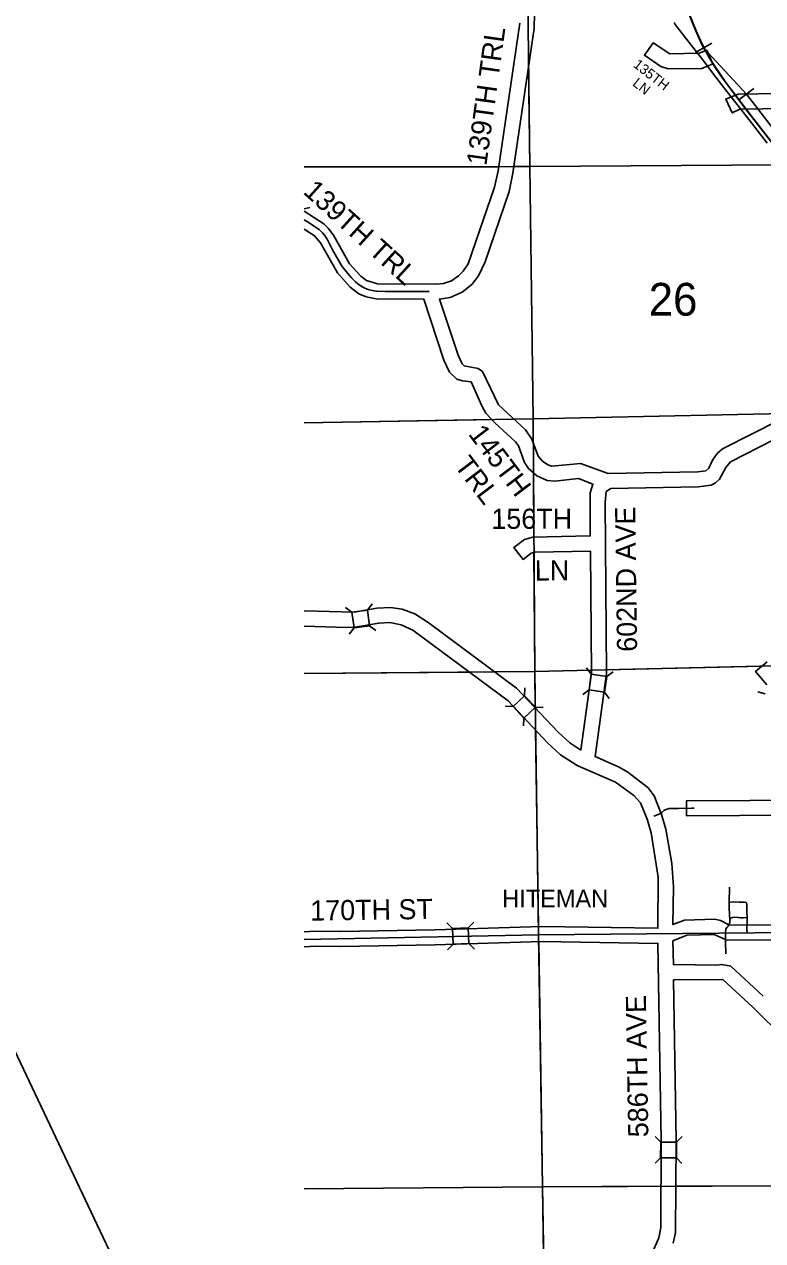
# Model space of a CAD drawing. Extents: x 10133 to 81668, y 5524 to 11018.
# Drawn here: x 14867 to 15234, y 8660 to 9263 of the extents above; entities that cross this region are included whole.
import ezdxf

# ---------------------------------------------------------------- set-up
doc = ezdxf.new("R2010")
doc.units = 0
doc.layers.add('Default', color=7, linetype='Continuous')
doc.layers.add('DisCLMLSUR', color=7, linetype='Continuous')

msp = doc.modelspace()

# ---------------------------------------------------------------- linework, layer by layer
at = {"layer": 'Default'}
for p, q in [((15200.49, 9249.38), (15208.67, 9253.96)), ((15222.05, 9225.78), (15229.55, 9231.4)), ((15006.1, 9171.72), (15008.99, 9172.37)), ((15029.84, 8971.49), (15026.72, 8973.85)), ((15037.59, 8972.57), (15039.95, 8975.69)), ((15030.92, 8963.74), (15028.56, 8960.62)), ((15038.67, 8964.82), (15041.79, 8962.46)), ((15148.73, 8940.71), (15146.38, 8943.84)), ((15156.48, 8939.6), (15159.61, 8941.95)), ((15115.64, 8930.05), (15115.78, 8933.96)), ((15147.63, 8932.96), (15144.5, 8930.61)), ((15155.37, 8931.86), (15157.72, 8928.73)), ((15235.18, 8930.94), (15231.43, 8932.07)), ((15109.91, 8924.72), (15106, 8924.86)), ((15120.97, 8924.32), (15124.88, 8924.18)), ((15115.24, 8918.99), (15115.1, 8915.08)), ((15079.84, 8814.61), (15077, 8817.3)), ((15087.67, 8814.84), (15090.35, 8817.69)), ((15080.08, 8806.79), (15077.39, 8803.94)), ((15087.9, 8807.02), (15090.74, 8804.34)), ((15183.28, 8708.55), (15180.54, 8711.35)), ((15191.11, 8708.48), (15193.9, 8711.23)), ((15183.21, 8700.73), (15180.42, 8697.99)), ((15191.04, 8700.66), (15193.78, 8697.87))]:
    msp.add_line(p, q, dxfattribs=at)
for points in [[(15308.74, 9284.89), (15310.88, 9134.18), (15309.62, 9131.25), (15307.07, 9129.14), (15304.36, 9128.64), (15294.54, 9128.72), (15290.44, 9126.84), (15287.3, 9133.64), (15293.09, 9136.14), (15303.47, 9136.14), (15302.03, 9222.4), (15222.5, 9221.13), (15218.75, 9219.37), (15215.57, 9226.16), (15221.63, 9228.62), (15301.85, 9229.9), (15299.87, 9396.97)], [(15116.72, 9317.83), (15118.18, 9192.67)], [(15376.46, 9026.55), (15227.85, 9218.32), (15215.51, 9234.43), (15207.49, 9246.48), (15203.98, 9253.08), (15201.14, 9259.29), (15192.64, 9280.57)], [(15120.76, 9276.61), (15120.45, 9261.26), (15109.87, 9189.44), (15107.94, 9180.34), (15096.11, 9145.44), (15092.8, 9138.48), (15089.43, 9134.22), (15084.7, 9130.38), (15078.62, 9127.72), (15073.37, 9126.93), (15082.58, 9099.07), (15084.63, 9094.81), (15085.55, 9093.84), (15092.65, 9092.53), (15094.67, 9091), (15102.68, 9074.49), (15116.02, 9062.03), (15119.26, 9057.46), (15122.33, 9049), (15124.55, 9046.42), (15127.11, 9044.71), (15129.24, 9044.08), (15143.48, 9045.28), (15157.21, 9040.31), (15201.69, 9041.2), (15205.72, 9041.69), (15207.11, 9042.96), (15208.99, 9046.93), (15211.29, 9050.34), (15213.92, 9052.55), (15242.75, 9067.24)], [(15197.04, 9269.01), (15199.73, 9262.37), (15201.67, 9257.74), (15204, 9252.71), (15207.79, 9245.94), (15210.65, 9241.42), (15213.88, 9236.66), (15221.86, 9226.01), (15225.4, 9221.29), (15238.22, 9204.83)], [(15006.1, 9170.58), (15015.99, 9164.24), (15018.14, 9162.2), (15020.65, 9158.71), (15028.64, 9144.47), (15034.24, 9138.24), (15037.07, 9136.09), (15042.57, 9134.55), (15071.56, 9134.32), (15075.28, 9134.66), (15079.34, 9135.96), (15082.89, 9138.41), (15085.18, 9140.81), (15087.65, 9144.48), (15100.77, 9182.53), (15102.46, 9190.56), (15113.23, 9263.88)], [(15236.12, 9204.25), (15231.16, 9210.78), (15226.04, 9217.35), (15220.56, 9224.35), (15216.3, 9229.8), (15210.69, 9237.05), (15206.46, 9242.53), (15204.14, 9245.6), (15202.86, 9247.28), (15198.51, 9252.86), (15195.49, 9256.68), (15192.69, 9260.32), (15191.92, 9261.25), (15191.19, 9262.21), (15190.5, 9263.2), (15189.86, 9264.22)], [(15198.39, 9265.69), (15199.73, 9262.37), (15200.7, 9260.06), (15201.67, 9257.74), (15202.83, 9255.23), (15204, 9252.71), (15204.57, 9251.65), (15225.77, 9228.6), (15244.84, 9203.95)], [(15186.91, 9241.18), (15183.34, 9242.31), (15175.12, 9247.96), (15179.45, 9254.08), (15187.76, 9248.63), (15202.38, 9248.92), (15206.1, 9250.52), (15209.06, 9243.63), (15203.65, 9241.44), (15186.91, 9241.18)], [(15117.6, 9242.22), (15118.18, 9192.67)], [(15006.1, 9192.52), (15118.18, 9192.67)], [(15006.1, 9192.52), (15102.76, 9192.65)], [(15110.34, 9192.66), (15118.18, 9192.67)], [(15118.18, 9192.67), (15243.7, 9193.61)], [(15118.18, 9192.67), (15243.7, 9193.61)], [(15118.18, 9192.67), (15119.9, 9067.44)], [(15118.18, 9192.67), (15119.9, 9067.44)], [(15006.1, 9166.29), (15007.76, 9165.24), (15013.56, 9161.39), (15014.39, 9160.68), (15015.25, 9159.82), (15016.27, 9158.58), (15017.5, 9156.67), (15018, 9155.66), (15020.25, 9151.4), (15024.65, 9143.6), (15025.64, 9142.22), (15026.94, 9140.58), (15029.74, 9137.47), (15031.65, 9135.53), (15032.85, 9134.45), (15034.46, 9133.34), (15035.23, 9132.81), (15036.58, 9132.2), (15037.91, 9131.67), (15039.3, 9131.3), (15040.9, 9131), (15042.26, 9130.81), (15046.32, 9130.69), (15054.28, 9130.69), (15063.22, 9130.72), (15068.32, 9130.62)], [(15143.5, 8903.07), (15148.8, 8941.42), (15148.36, 9001.85), (15120.8, 9001.34), (15118.87, 9000.75), (15114.98, 8997.7), (15110.35, 9003.6), (15115.61, 9007.53), (15119.72, 9008.76), (15148.27, 9009.35), (15148.28, 9030.81), (15149.6, 9035.02), (15142.38, 9037.85), (15130.71, 9036.54), (15126.85, 9036.83), (15121.79, 9039.18), (15117.51, 9042.82), (15115.57, 9045.75), (15112.58, 9054.03), (15111.15, 9056.07), (15100.85, 9065.55), (15096.45, 9070.3), (15094.33, 9073.91), (15089.1, 9085.79), (15084.85, 9086.3), (15081.96, 9087.19), (15078.36, 9090.69), (15075.49, 9096.61), (15065.53, 9126.93), (15041.95, 9127.07), (15036.94, 9128.05), (15033.39, 9129.55), (15028.98, 9132.9), (15022.7, 9139.89), (15014.23, 9154.83), (15011.3, 9158.39), (15006.1, 9161.67)], [(15119.9, 9067.44), (15245.03, 9070.19)], [(15119.9, 9067.44), (15245.03, 9070.19)], [(15006.1, 9065.58), (15119.9, 9067.44)], [(15006.1, 9065.58), (15099.31, 9067.1)], [(15110.24, 9067.28), (15119.9, 9067.44)], [(15119.9, 9067.44), (15119.97, 9055.74)], [(15119.9, 9067.44), (15120.64, 8942.07)], [(15246.38, 9060.68), (15217.94, 9046.21), (15215.54, 9043.26), (15212.43, 9037.59), (15210.41, 9035.75), (15208.29, 9034.62), (15201.84, 9033.71), (15158.46, 9032.89), (15156.16, 9031.4), (15155.65, 9026.2), (15156.29, 8941.07), (15150.68, 8899.89), (15162.67, 8894.67), (15166.99, 8892.2), (15176.93, 8884.32), (15179.91, 8880.3), (15183.58, 8871.16), (15185.76, 8863.81), (15188.71, 8846.85), (15189.62, 8835.28), (15189.33, 8816.49), (15195.07, 8818.68), (15210.07, 8819.13), (15213.01, 8818.52), (15217, 8816.29), (15251.89, 8816.2)], [(15120.06, 9040.44), (15120.25, 9008.75)], [(15120.29, 9001.15), (15120.64, 8942.07)], [(15006.1, 8972.19), (15030.92, 8971.5), (15042.27, 8973.53), (15048.96, 8973.89), (15054.78, 8973.02), (15061.07, 8970.67), (15068.21, 8966.1), (15111.62, 8933.86), (15132.37, 8911.96), (15138.1, 8906.65), (15143.5, 8903.07)], [(15006.1, 8812.91), (15011.47, 8813.17), (15024.17, 8813.03), (15071, 8813.95), (15123.97, 8815.52), (15181.83, 8814.63), (15181.94, 8840.09), (15178.48, 8862), (15176.48, 8868.73), (15173.2, 8876.94), (15169.92, 8880.56), (15160.81, 8887.16), (15141.79, 8895.51), (15133.52, 8900.71), (15126.97, 8906.76), (15107.53, 8927.51), (15060.18, 8962.63), (15054.29, 8965.32), (15048.69, 8966.39), (15043.2, 8966.09), (15031.51, 8964.02), (15027.43, 8963.99), (15006.1, 8964.64)], [(15006.1, 8941.04), (15120.64, 8942.07)], [(15006.1, 8941.04), (15088.35, 8941.78)], [(15006.1, 8941.04), (15088.36, 8941.78)], [(15100.94, 8941.89), (15120.64, 8942.07)], [(15120.64, 8942.07), (15246.45, 8945)], [(15120.64, 8942.07), (15148.8, 8942.72)], [(15120.64, 8942.07), (15120.91, 8924.2)], [(15120.64, 8942.07), (15122.61, 8811.46)], [(15156.29, 8942.9), (15233.47, 8944.69)], [(15236.02, 8935.41), (15230.39, 8942.11), (15236.13, 8946.93)], [(15121.08, 8913.05), (15122.55, 8815.43)], [(15274.86, 8870.91), (15196.08, 8870.45), (15196.12, 8877.95), (15258.97, 8878.25)], [(15179.89, 8870.33), (15181.15, 8870.7), (15182.35, 8871.26), (15183.73, 8872.18), (15184.75, 8873.04), (15185.99, 8873.6), (15187.46, 8874.15), (15192, 8874.03), (15198.56, 8874.19), (15199.75, 8874.18), (15199.85, 8874.18)], [(15217.31, 8827.48), (15217.34, 8835.05)], [(15226.11, 8820.06), (15226.03, 8822.99), (15226, 8825.31), (15226.03, 8826.63), (15225.82, 8827.31), (15225.72, 8827.41), (15225.63, 8827.49), (15224.77, 8827.68), (15222.15, 8827.65), (15219.31, 8827.74), (15218.08, 8827.65), (15217.31, 8827.48)], [(15217.51, 8819.12), (15217.43, 8820.77), (15217.31, 8825.64), (15217.31, 8827.48)], [(15215.37, 8807.81), (15215.37, 8811.03), (15215.5, 8812.85), (15215.58, 8813.99), (15215.74, 8814.52), (15216.14, 8815.04), (15216.72, 8815.75), (15217.06, 8816.3), (15217.4, 8817.01), (15217.56, 8817.78), (15217.52, 8818.89), (15217.51, 8819.12)], [(15217.51, 8819.12), (15217.96, 8819.63), (15218.82, 8820.03), (15219.84, 8820.13), (15221.84, 8820.07), (15222.86, 8819.88), (15224.15, 8819.85), (15226.11, 8820.06)], [(15226.16, 8812.44), (15226.03, 8813.87), (15226.16, 8818.09), (15226.11, 8820.06)], [(15006.1, 8809.07), (15122.61, 8811.46)], [(15122.61, 8811.46), (15247.8, 8812.53)], [(15122.61, 8811.46), (15124.6, 8686.39)], [(15251.51, 8808.71), (15215.69, 8808.86), (15209.83, 8811.63), (15196.19, 8811.26), (15189.32, 8808.34), (15189.53, 8796.61), (15211.19, 8796.41), (15213.59, 8796.74), (15218.09, 8795.78), (15234.17, 8781)], [(15179.26, 8654.2), (15182.39, 8660.98), (15183.26, 8666.09), (15183.45, 8709.31), (15181.83, 8807.13), (15124.23, 8808.02), (15071.11, 8806.45), (15024.29, 8805.53), (15011.74, 8805.68), (15006.1, 8805.4)], [(15122.67, 8807.92), (15124.6, 8686.39)], [(15215.61, 8801.9), (15215.55, 8802.74), (15215.37, 8807.33), (15215.37, 8807.81)], [(15244.75, 8759.96), (15229.06, 8775.51), (15214.16, 8789.15), (15189.65, 8789.11), (15190.95, 8709.37), (15190.61, 8663.67), (15189.4, 8658.29)], [(15006.1, 8685.38), (15124.6, 8686.39)], [(15006.1, 8685.38), (15124.6, 8686.39)], [(15124.6, 8686.39), (15250.81, 8686.88)], [(15124.6, 8686.39), (15183.36, 8686.62)], [(15124.6, 8686.39), (15125.11, 8648.26)], [(15124.6, 8686.39), (15126.27, 8562.47)], [(15190.89, 8686.65), (15250.81, 8686.88)]]:
    msp.add_lwpolyline(points, dxfattribs=at)
for points in [[(15029.84, 8971.49), (15037.59, 8972.57), (15038.67, 8964.82), (15030.92, 8963.74)], [(15147.63, 8932.96), (15148.73, 8940.71), (15156.48, 8939.6), (15155.37, 8931.86)], [(15115.64, 8930.05), (15120.97, 8924.32), (15115.24, 8918.99), (15109.91, 8924.72)], [(15079.84, 8814.61), (15087.67, 8814.84), (15087.9, 8807.02), (15080.08, 8806.79)], [(15183.21, 8700.73), (15183.28, 8708.55), (15191.11, 8708.48), (15191.04, 8700.66)]]:
    msp.add_lwpolyline(points, close=True, dxfattribs=at)
at = {"layer": 'DisCLMLSUR'}
msp.add_line((14949.85, 8569.5), (14513.59, 9488.76), dxfattribs=at)

# ---------------------------------------------------------------- texts
at = {"layer": 'Default'}
for s, height, rotation, p in [('139TH TRL', 10, 82.10404, (15096.63, 9192.85)), ('135TH', 5, 321.97164, (15169.2, 9242.51)), ('LN', 5, 321.97164, (15168.88, 9233.24)), ('139TH TRL', 10, 317.7292, (15005.2, 9179.66)), ('26', 16.25, 0.02474, (15177.29, 9118.71)), ('145TH', 10, 307.24949, (15087.32, 9059.87)), ('TRL', 10, 307.24949, (15080.38, 9044.22)), ('156TH', 10, 0.05228, (15099.13, 9012.89)), ('602ND AVE', 10, 90.79489, (15171.55, 8951.92)), ('LN', 10, 0.05228, (15120.7, 8987.25)), ('HITEMAN', 8.75, 0.02449, (15104.5, 8825.01)), ('170TH ST', 10, 0.80013, (15009.22, 8818.42)), ('586TH AVE', 10, 91, (15177.12, 8711))]:
    msp.add_text(s, height=height, rotation=rotation, dxfattribs=at).set_placement(p)

doc.saveas('drawing.dxf')
